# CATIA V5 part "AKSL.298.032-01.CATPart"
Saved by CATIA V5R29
Part number: АКСЛ.298.032-01
Material "Steel": density 7860 kg/m3, Young's modulus 2e+11 Pa, Poisson ratio 0.266, thermal expansion 1.17e-05 1/K
Bounding box of the stored display mesh (mm): x -149 to 149, y -51 to 52, z -52 to 51
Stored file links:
  Z:\ООО Аксель\Соединения бруса\Соединения бруса\Соединения из листа\АКСЛ.298.030 (Трио)\AKSL.298.032-01.CATPart
  Z:\ООО Аксель\Соединения бруса\Соединения бруса\Соединения из листа\АКСЛ.298.030 (Трио)\AKSL.298.032.CATPart
  Z:\ООО Аксель\Соединения бруса\Соединения бруса\Соединения из листа\АКСЛ.298.030 (Трио)\AKSL.298.030.CATProduct
  Z:\#Catalog_GosNIIAS\Holes&Pockets\Part\Соединение шип-паз\Ship-Paz.CATPart
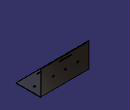
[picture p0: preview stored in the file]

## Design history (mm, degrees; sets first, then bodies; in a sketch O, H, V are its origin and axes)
External parameters (linked from other documents)
  `External.S металла` = 2 mm
  `External.R гиба` = 1.9 mm
  `External.K factor` = 0.49
SheetMetalParameters1: Thickness 2 {= `External.S металла`}, BendRadius 1.9 {= `External.R гиба`}, KFactor 0.49 {= `External.K factor`}, ReliefRadialLength 1, ReliefAxialLength 2, MinimumBendRadius 0
Set1
  DatumCurve1: linked copy from another document
  DatumCurve2: linked copy from another document
Set2 "External References"
  DatumSurface1 "Extrude.1": linked copy from another document
  DatumCurve3 "2 угол Profile.2": linked copy from another document
  Plane1 "OutputPlane.1 (Line.4)": linked copy from another document
Body1 (main body)
  Body2 "Body from original PartBody"
    Solid1: linked copy from another document
  Assemble1: tool Body2
  Recognize1: Recognize_BendTable SheetMetalParameters1, Recognize_ReferenceFace face of Solid1, Recognize_BendDefaultRadius 1.9 {= `External.R гиба`}, KFacteur 0.49 {= SheetMetalParameters1.KFactor}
